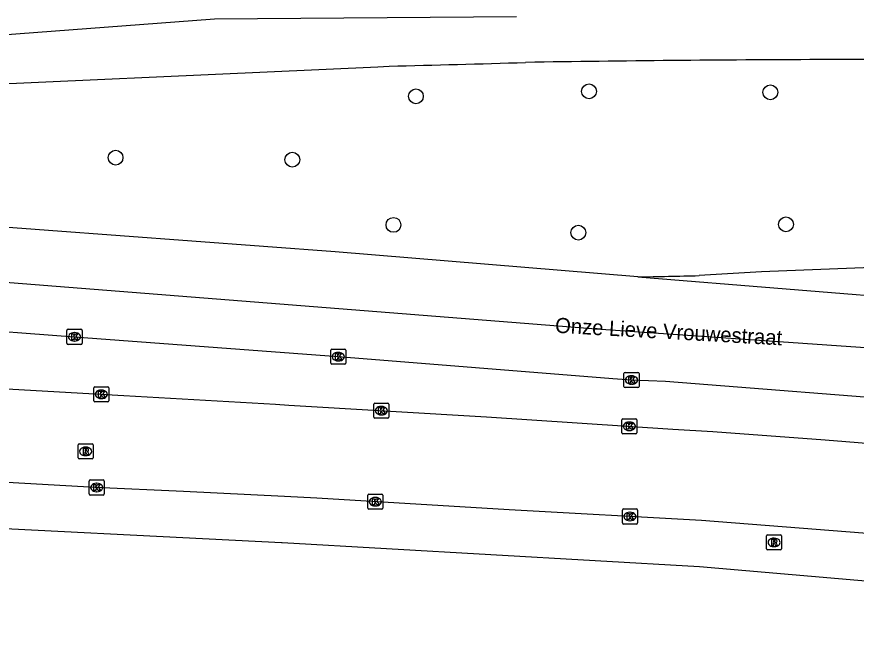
# Model space of a CAD drawing. Extents: x 161243 to 161752, y 384138 to 384885.
# Drawn here: x 161530.1 to 161585.6, y 384837.7 to 384878.9 of the extents above; entities that cross this region are included whole.
import ezdxf

# ---------------------------------------------------------------- set-up
doc = ezdxf.new("R2010")
doc.units = 0
for name, color, linetype in [('IMGEO_Boom', 7, 'Continuous'), ('IMGEO_Kolk', 7, 'Continuous'), ('IMGEO_Openbare_ruimte_label', 7, 'Continuous'), ('IMGEO_Rijbaan_lokaal_open', 7, 'Continuous'), ('IMGEO_Rijbaan_regionaal_gesloten', 7, 'Continuous'), ('IMGEO_Rioolput', 7, 'Continuous'), ('IMGEO_Voetpad_open', 7, 'Continuous')]:
    doc.layers.add(name, color=color, linetype=linetype)

msp = doc.modelspace()

# ---------------------------------------------------------------- linework, layer by layer
at = {"layer": 'IMGEO_Boom'}
for centre in [(161556.501, 384873.684), (161567.935, 384874.007), (161579.91, 384873.948), (161536.666, 384869.629), (161548.337, 384869.493), (161555.019, 384865.185), (161580.94, 384865.219), (161567.233, 384864.672)]:
    msp.add_circle(centre, 0.489, dxfattribs=at)
at = {"layer": 'IMGEO_Kolk'}
for p, q in [((161533.454, 384857.365), (161533.454, 384858.217)), ((161533.529, 384858.291), (161534.381, 384858.291)), ((161533.942, 384858.071), (161533.967, 384858.071)), ((161534.455, 384858.217), (161534.455, 384857.365)), ((161533.965, 384857.511), (161533.94, 384857.511)), ((161534.381, 384857.291), (161533.529, 384857.291)), ((161550.872, 384856.052), (161550.872, 384856.904)), ((161550.947, 384856.978), (161551.799, 384856.978)), ((161551.873, 384856.904), (161551.873, 384856.052)), ((161551.36, 384856.758), (161551.385, 384856.758)), ((161551.799, 384855.978), (161550.947, 384855.978)), ((161551.383, 384856.198), (161551.358, 384856.198)), ((161570.241, 384854.51), (161570.241, 384855.362)), ((161570.316, 384855.436), (161571.168, 384855.436)), ((161570.729, 384855.216), (161570.754, 384855.216)), ((161571.242, 384855.362), (161571.242, 384854.51)), ((161570.752, 384854.656), (161570.727, 384854.656)), ((161535.222, 384853.563), (161535.222, 384854.415)), ((161535.297, 384854.489), (161536.149, 384854.489)), ((161535.71, 384854.269), (161535.735, 384854.269)), ((161536.223, 384854.415), (161536.223, 384853.563)), ((161571.168, 384854.436), (161570.316, 384854.436)), ((161535.733, 384853.709), (161535.708, 384853.709)), ((161536.149, 384853.489), (161535.297, 384853.489)), ((161553.718, 384852.484), (161553.718, 384853.336)), ((161553.793, 384853.41), (161554.645, 384853.41)), ((161554.206, 384853.19), (161554.231, 384853.19)), ((161554.719, 384853.336), (161554.719, 384852.484)), ((161554.229, 384852.63), (161554.204, 384852.63)), ((161554.645, 384852.41), (161553.793, 384852.41)), ((161570.098, 384851.453), (161570.098, 384852.305)), ((161570.173, 384852.379), (161571.025, 384852.379)), ((161570.586, 384852.159), (161570.611, 384852.159)), ((161571.099, 384852.305), (161571.099, 384851.453)), ((161571.025, 384851.379), (161570.173, 384851.379)), ((161570.609, 384851.599), (161570.584, 384851.599)), ((161534.918, 384847.403), (161534.918, 384848.255)), ((161534.993, 384848.329), (161535.845, 384848.329)), ((161535.406, 384848.109), (161535.431, 384848.109)), ((161535.919, 384848.255), (161535.919, 384847.403)), ((161535.429, 384847.549), (161535.404, 384847.549)), ((161535.845, 384847.329), (161534.993, 384847.329)), ((161553.319, 384846.466), (161553.319, 384847.318)), ((161553.394, 384847.392), (161554.246, 384847.392)), ((161553.807, 384847.172), (161553.832, 384847.172)), ((161554.32, 384847.318), (161554.32, 384846.466)), ((161554.246, 384846.392), (161553.394, 384846.392)), ((161553.83, 384846.612), (161553.805, 384846.612)), ((161570.136, 384845.491), (161570.136, 384846.343)), ((161570.211, 384846.417), (161571.063, 384846.417)), ((161571.137, 384846.343), (161571.137, 384845.491)), ((161570.624, 384846.197), (161570.649, 384846.197)), ((161571.063, 384845.417), (161570.211, 384845.417)), ((161570.647, 384845.637), (161570.622, 384845.637))]:
    msp.add_line(p, q, dxfattribs=at)
for points in [[(161533.454, 384857.365), (161533.454, 384858.217)], [(161533.529, 384858.291), (161534.381, 384858.291)], [(161533.775, 384857.991), (161533.898, 384857.991), (161533.898, 384857.84), (161534.028, 384857.991), (161534.192, 384857.991), (161534.046, 384857.84), (161534.199, 384857.591), (161534.047, 384857.591), (161533.962, 384857.755), (161533.898, 384857.688), (161533.898, 384857.591), (161533.775, 384857.591), (161533.775, 384857.991)], [(161534.455, 384858.217), (161534.455, 384857.365)], [(161534.381, 384857.291), (161533.529, 384857.291)], [(161550.872, 384856.052), (161550.872, 384856.904)], [(161550.947, 384856.978), (161551.799, 384856.978)], [(161551.873, 384856.904), (161551.873, 384856.052)], [(161551.193, 384856.678), (161551.316, 384856.678), (161551.316, 384856.527), (161551.446, 384856.678), (161551.61, 384856.678), (161551.464, 384856.527), (161551.617, 384856.278), (161551.465, 384856.278), (161551.38, 384856.442), (161551.316, 384856.375), (161551.316, 384856.278), (161551.193, 384856.278), (161551.193, 384856.678)], [(161551.799, 384855.978), (161550.947, 384855.978)], [(161570.241, 384854.51), (161570.241, 384855.362)], [(161570.316, 384855.436), (161571.168, 384855.436)], [(161571.242, 384855.362), (161571.242, 384854.51)], [(161570.562, 384855.136), (161570.685, 384855.136), (161570.685, 384854.985), (161570.815, 384855.136), (161570.979, 384855.136), (161570.833, 384854.985), (161570.986, 384854.736), (161570.834, 384854.736), (161570.749, 384854.9), (161570.685, 384854.833), (161570.685, 384854.736), (161570.562, 384854.736), (161570.562, 384855.136)], [(161535.222, 384853.563), (161535.222, 384854.415)], [(161535.297, 384854.489), (161536.149, 384854.489)], [(161535.543, 384854.189), (161535.666, 384854.189), (161535.666, 384854.038), (161535.796, 384854.189), (161535.96, 384854.189), (161535.814, 384854.038), (161535.967, 384853.789), (161535.815, 384853.789), (161535.73, 384853.953), (161535.666, 384853.886), (161535.666, 384853.789), (161535.543, 384853.789), (161535.543, 384854.189)], [(161536.223, 384854.415), (161536.223, 384853.563)], [(161571.168, 384854.436), (161570.316, 384854.436)], [(161536.149, 384853.489), (161535.297, 384853.489)], [(161553.718, 384852.484), (161553.718, 384853.336)], [(161553.793, 384853.41), (161554.645, 384853.41)], [(161554.039, 384853.11), (161554.162, 384853.11), (161554.162, 384852.959), (161554.292, 384853.11), (161554.456, 384853.11), (161554.31, 384852.959), (161554.463, 384852.71), (161554.311, 384852.71), (161554.226, 384852.874), (161554.162, 384852.807), (161554.162, 384852.71), (161554.039, 384852.71), (161554.039, 384853.11)], [(161554.719, 384853.336), (161554.719, 384852.484)], [(161554.645, 384852.41), (161553.793, 384852.41)], [(161570.098, 384851.453), (161570.098, 384852.305)], [(161570.173, 384852.379), (161571.025, 384852.379)], [(161570.419, 384852.079), (161570.542, 384852.079), (161570.542, 384851.928), (161570.672, 384852.079), (161570.836, 384852.079), (161570.69, 384851.928), (161570.843, 384851.679), (161570.691, 384851.679), (161570.606, 384851.843), (161570.542, 384851.776), (161570.542, 384851.679), (161570.419, 384851.679), (161570.419, 384852.079)], [(161571.099, 384852.305), (161571.099, 384851.453)], [(161571.025, 384851.379), (161570.173, 384851.379)], [(161534.918, 384847.403), (161534.918, 384848.255)], [(161534.993, 384848.329), (161535.845, 384848.329)], [(161535.239, 384848.029), (161535.362, 384848.029), (161535.362, 384847.878), (161535.492, 384848.029), (161535.656, 384848.029), (161535.51, 384847.878), (161535.663, 384847.629), (161535.511, 384847.629), (161535.426, 384847.793), (161535.362, 384847.726), (161535.362, 384847.629), (161535.239, 384847.629), (161535.239, 384848.029)], [(161535.919, 384848.255), (161535.919, 384847.403)], [(161535.845, 384847.329), (161534.993, 384847.329)], [(161553.319, 384846.466), (161553.319, 384847.318)], [(161553.394, 384847.392), (161554.246, 384847.392)], [(161553.64, 384847.092), (161553.763, 384847.092), (161553.763, 384846.941), (161553.893, 384847.092), (161554.057, 384847.092), (161553.911, 384846.941), (161554.064, 384846.692), (161553.912, 384846.692), (161553.827, 384846.856), (161553.763, 384846.789), (161553.763, 384846.692), (161553.64, 384846.692), (161553.64, 384847.092)], [(161554.32, 384847.318), (161554.32, 384846.466)], [(161554.246, 384846.392), (161553.394, 384846.392)], [(161570.136, 384845.491), (161570.136, 384846.343)], [(161570.211, 384846.417), (161571.063, 384846.417)], [(161571.137, 384846.343), (161571.137, 384845.491)], [(161570.457, 384846.117), (161570.58, 384846.117), (161570.58, 384845.966), (161570.71, 384846.117), (161570.874, 384846.117), (161570.728, 384845.966), (161570.881, 384845.717), (161570.729, 384845.717), (161570.644, 384845.881), (161570.58, 384845.814), (161570.58, 384845.717), (161570.457, 384845.717), (161570.457, 384846.117)], [(161571.063, 384845.417), (161570.211, 384845.417)]]:
    msp.add_lwpolyline(points, dxfattribs=at)
for centre, start, end in [((161533.531, 384858.215), 91.552, 178.448), ((161533.531, 384858.215), 91.552, 178.448), ((161534.379, 384858.215), 1.552, 88.448), ((161534.379, 384858.215), 1.552, 88.448), ((161533.531, 384857.367), 181.552, 268.448), ((161533.531, 384857.367), 181.552, 268.448), ((161534.379, 384857.367), 271.552, 358.448), ((161534.379, 384857.367), 271.552, 358.448), ((161550.949, 384856.902), 91.552, 178.448), ((161550.949, 384856.902), 91.552, 178.448), ((161551.797, 384856.902), 1.552, 88.448), ((161551.797, 384856.902), 1.552, 88.448), ((161550.949, 384856.054), 181.552, 268.448), ((161550.949, 384856.054), 181.552, 268.448), ((161551.797, 384856.054), 271.552, 358.448), ((161551.797, 384856.054), 271.552, 358.448), ((161570.318, 384855.36), 91.552, 178.448), ((161570.318, 384855.36), 91.552, 178.448), ((161571.166, 384855.36), 1.552, 88.448), ((161571.166, 384855.36), 1.552, 88.448), ((161535.299, 384854.413), 91.552, 178.448), ((161535.299, 384854.413), 91.552, 178.448), ((161536.147, 384854.413), 1.552, 88.448), ((161536.147, 384854.413), 1.552, 88.448), ((161570.318, 384854.512), 181.552, 268.448), ((161570.318, 384854.512), 181.552, 268.448), ((161571.166, 384854.512), 271.552, 358.448), ((161571.166, 384854.512), 271.552, 358.448), ((161535.299, 384853.565), 181.552, 268.448), ((161535.299, 384853.565), 181.552, 268.448), ((161536.147, 384853.565), 271.552, 358.448), ((161536.147, 384853.565), 271.552, 358.448), ((161553.795, 384853.334), 91.552, 178.448), ((161553.795, 384853.334), 91.552, 178.448), ((161554.643, 384853.334), 1.552, 88.448), ((161554.643, 384853.334), 1.552, 88.448), ((161553.795, 384852.486), 181.552, 268.448), ((161553.795, 384852.486), 181.552, 268.448), ((161554.643, 384852.486), 271.552, 358.448), ((161554.643, 384852.486), 271.552, 358.448), ((161570.175, 384852.303), 91.552, 178.448), ((161570.175, 384852.303), 91.552, 178.448), ((161571.023, 384852.303), 1.552, 88.448), ((161571.023, 384852.303), 1.552, 88.448), ((161570.175, 384851.455), 181.552, 268.448), ((161570.175, 384851.455), 181.552, 268.448), ((161571.023, 384851.455), 271.552, 358.448), ((161571.023, 384851.455), 271.552, 358.448), ((161534.995, 384848.253), 91.552, 178.448), ((161534.995, 384848.253), 91.552, 178.448), ((161535.843, 384848.253), 1.552, 88.448), ((161535.843, 384848.253), 1.552, 88.448), ((161534.995, 384847.405), 181.552, 268.448), ((161534.995, 384847.405), 181.552, 268.448), ((161535.843, 384847.405), 271.552, 358.448), ((161535.843, 384847.405), 271.552, 358.448), ((161553.396, 384847.316), 91.552, 178.448), ((161553.396, 384847.316), 91.552, 178.448), ((161554.244, 384847.316), 1.552, 88.448), ((161554.244, 384847.316), 1.552, 88.448), ((161553.396, 384846.468), 181.552, 268.448), ((161553.396, 384846.468), 181.552, 268.448), ((161554.244, 384846.468), 271.552, 358.448), ((161554.244, 384846.468), 271.552, 358.448), ((161570.213, 384846.341), 91.552, 178.448), ((161570.213, 384846.341), 91.552, 178.448), ((161571.061, 384846.341), 1.552, 88.448), ((161571.061, 384846.341), 1.552, 88.448), ((161570.213, 384845.493), 181.552, 268.448), ((161570.213, 384845.493), 181.552, 268.448), ((161571.061, 384845.493), 271.552, 358.448), ((161571.061, 384845.493), 271.552, 358.448)]:
    msp.add_arc(centre, 0.0765, start, end, dxfattribs=at)
for centre, major_axis, ratio, start_param, end_param in [((161533.941, 384857.791), (-0.387, 0.002), 0.722429, 4.712389, 7.853982), ((161533.966, 384857.791), (-0.39, 0.002), 0.717154, 1.570796, 4.712389), ((161551.359, 384856.478), (-0.387, 0.002), 0.722429, 4.712389, 7.853982), ((161551.384, 384856.478), (-0.39, 0.002), 0.717154, 1.570796, 4.712389), ((161570.728, 384854.936), (-0.387, 0.002), 0.722429, 4.712389, 7.853982), ((161570.753, 384854.936), (-0.39, 0.002), 0.717154, 1.570796, 4.712389), ((161535.709, 384853.989), (-0.387, 0.002), 0.722429, 4.712389, 7.853982), ((161535.734, 384853.989), (-0.39, 0.002), 0.717154, 1.570796, 4.712389), ((161554.205, 384852.91), (-0.387, 0.002), 0.722429, 4.712389, 7.853982), ((161554.23, 384852.91), (-0.39, 0.002), 0.717154, 1.570796, 4.712389), ((161570.585, 384851.879), (-0.387, 0.002), 0.722429, 4.712389, 7.853982), ((161570.61, 384851.879), (-0.39, 0.002), 0.717154, 1.570796, 4.712389), ((161535.405, 384847.829), (-0.387, 0.002), 0.722429, 4.712389, 7.853982), ((161535.43, 384847.829), (-0.39, 0.002), 0.717154, 1.570796, 4.712389), ((161553.806, 384846.892), (-0.387, 0.002), 0.722429, 4.712389, 7.853982), ((161553.831, 384846.892), (-0.39, 0.002), 0.717154, 1.570796, 4.712389), ((161570.623, 384845.917), (-0.387, 0.002), 0.722429, 4.712389, 7.853982), ((161570.648, 384845.917), (-0.39, 0.002), 0.717154, 1.570796, 4.712389)]:
    msp.add_ellipse(centre, major_axis=major_axis, ratio=ratio, start_param=start_param, end_param=end_param, dxfattribs=at)
at = {"layer": 'IMGEO_Rijbaan_lokaal_open'}
for points in [[(161432.691, 384858.617), (161443.897, 384858.139), (161457.123, 384857.598), (161464.496, 384857.284), (161488.747, 384856.252), (161495.954, 384855.908), (161500.984, 384855.619), (161518.06, 384854.968), (161526.784, 384854.51), (161537.21, 384853.901), (161547.23, 384853.329), (161548.117, 384853.276), (161561.161, 384852.491), (161573.48, 384851.691), (161576.121, 384851.539), (161583.525, 384850.98), (161591.436, 384850.345), (161599.97, 384849.634), (161609.304, 384848.897), (161621.915, 384847.716), (161637.662, 384846.256), (161645.218, 384845.76), (161654.603, 384845.532), (161661.029, 384846.084)], [(161632.436, 384840.682), (161616.429, 384842.146), (161606.018, 384843.165), (161590.517, 384844.456), (161575.357, 384845.656), (161562.667, 384846.361), (161549.947, 384847.125), (161547.823, 384847.234), (161541.147, 384847.577), (161535.307, 384847.835), (161519.427, 384848.731), (161508.267, 384849.216), (161502.488, 384849.552), (161500, 384849.668), (161499.426, 384849.695)]]:
    msp.add_lwpolyline(points, dxfattribs=at)
at = {"layer": 'IMGEO_Rijbaan_regionaal_gesloten'}
for points in [[(161563.138, 384878.938), (161543.2, 384878.777), (161524.222, 384877.345), (161512.226, 384876.808), (161497.186, 384877.166), (161481.609, 384877.166), (161467.536, 384877.915), (161467.518, 384877.993)], [(161494.845, 384873.396), (161507.854, 384873.67), (161520.825, 384874.142), (161553.985, 384875.638), (161554.741, 384875.672)], [(161571.148, 384861.746), (161551.158, 384863.399), (161532.245, 384864.805), (161511.027, 384866.396), (161504.31, 384866.9), (161484.365, 384868.354), (161483.247, 384868.441)], [(161720.414, 384842.06), (161663.633, 384849.838), (161597.297, 384856.281), (161568.402, 384858.295), (161503.74, 384863.414), (161467.959, 384864.205)], [(161654.748, 384858.736), (161646.577, 384859.324), (161637.725, 384859.857), (161625.166, 384860.619), (161617.076, 384861.152), (161611.12, 384861.635), (161603.971, 384862.003), (161595.945, 384862.435), (161592.236, 384862.6), (161579.329, 384862.087), (161575.207, 384861.834)], [(161571.148, 384861.746), (161610.346, 384858.579), (161622.051, 384857.564), (161629.564, 384856.913), (161674.127, 384851.959), (161681.32, 384851.152)], [(161499.371, 384860.47), (161509.567, 384859.646), (161533.955, 384857.791), (161551.373, 384856.478), (161569.508, 384855.04), (161570.742, 384854.936), (161572.993, 384854.851), (161590.878, 384853.444), (161606.841, 384852.059), (161622.232, 384850.751), (161627.655, 384850.205), (161638.043, 384849.1), (161645.472, 384848.465), (161650.082, 384848.059), (161654.755, 384847.767), (161654.704, 384847.64), (161659.708, 384847.081), (161661.029, 384846.96)]]:
    msp.add_lwpolyline(points, dxfattribs=at)
for centre, radius, start, end in [((161496.306, 387152.999), 2278.077, 271.469861, 271.696532), ((161586.952, 383468.163), 1407.949, 90.15553, 90.944232), ((161586.39, 384469.793), 406.327, 87.55773, 90.45974), ((161532.595, 386733.642), 1872.293, 271.179869, 271.304112)]:
    msp.add_arc(centre, radius, start, end, dxfattribs=at)
at = {"layer": 'IMGEO_Rioolput'}
for p, q in [((161534.185, 384849.794), (161534.185, 384850.646)), ((161534.26, 384850.72), (161535.112, 384850.72)), ((161534.673, 384850.5), (161534.698, 384850.5)), ((161535.186, 384850.646), (161535.186, 384849.794)), ((161535.112, 384849.72), (161534.26, 384849.72)), ((161534.696, 384849.94), (161534.671, 384849.94)), ((161579.731, 384844.703), (161580.583, 384844.703)), ((161579.656, 384843.777), (161579.656, 384844.629)), ((161580.144, 384844.483), (161580.169, 384844.483)), ((161580.657, 384844.629), (161580.657, 384843.777)), ((161580.583, 384843.703), (161579.731, 384843.703)), ((161580.167, 384843.923), (161580.142, 384843.923))]:
    msp.add_line(p, q, dxfattribs=at)
for points in [[(161534.185, 384849.794), (161534.185, 384850.646)], [(161534.26, 384850.72), (161535.112, 384850.72)], [(161534.774, 384850.418), (161534.522, 384850.42), (161534.522, 384850.02)], [(161534.7, 384850.339), (161534.646, 384850.339), (161534.646, 384850.258)], [(161534.646, 384850.258), (161534.698, 384850.258)], [(161535.186, 384850.646), (161535.186, 384849.794)], [(161535.112, 384849.72), (161534.26, 384849.72)], [(161534.522, 384850.02), (161534.646, 384850.02), (161534.646, 384850.182), (161534.657, 384850.182)], [(161534.704, 384850.153), (161534.775, 384850.02), (161534.915, 384850.02), (161534.85, 384850.146)], [(161579.731, 384844.703), (161580.583, 384844.703)], [(161579.656, 384843.777), (161579.656, 384844.629)], [(161580.245, 384844.401), (161579.993, 384844.403), (161579.993, 384844.003)], [(161579.993, 384844.003), (161580.117, 384844.003), (161580.117, 384844.165), (161580.128, 384844.165)], [(161580.171, 384844.322), (161580.117, 384844.322), (161580.117, 384844.241)], [(161580.117, 384844.241), (161580.169, 384844.241)], [(161580.175, 384844.136), (161580.246, 384844.003), (161580.386, 384844.003), (161580.321, 384844.129)], [(161580.657, 384844.629), (161580.657, 384843.777)], [(161580.583, 384843.703), (161579.731, 384843.703)]]:
    msp.add_lwpolyline(points, dxfattribs=at)
for centre, radius, start, end in [((161534.262, 384850.644), 0.0765, 91.552, 178.448), ((161534.262, 384850.644), 0.0765, 91.552, 178.448), ((161534.682, 384850.447), 0.19, 274.7715, 282.9687), ((161534.706, 384850.243), 0.0964, 77.0061, 93.1865), ((161534.72, 384850.3), 0.0378, 276.6634, 79.6772), ((161534.773, 384850.308), 0.109, 350.3612, 89.416), ((161534.771, 384850.308), 0.112, 277.5842, 350.9817), ((161535.11, 384850.644), 0.0765, 1.552, 88.448), ((161535.11, 384850.644), 0.0765, 1.552, 88.448), ((161534.262, 384849.796), 0.0765, 181.552, 268.448), ((161534.262, 384849.796), 0.0765, 181.552, 268.448), ((161534.656, 384850.129), 0.0533, 26.0293, 88.6989), ((161534.755, 384850.093), 0.108, 29.5134, 73.7905), ((161535.11, 384849.796), 0.0765, 271.552, 358.448), ((161535.11, 384849.796), 0.0765, 271.552, 358.448), ((161579.733, 384844.627), 0.0765, 91.552, 178.448), ((161579.733, 384844.627), 0.0765, 91.552, 178.448), ((161580.581, 384844.627), 0.0765, 1.552, 88.448), ((161580.581, 384844.627), 0.0765, 1.552, 88.448), ((161580.127, 384844.112), 0.0533, 26.0293, 88.6989), ((161580.153, 384844.43), 0.19, 274.7715, 282.9687), ((161580.177, 384844.226), 0.0964, 77.0061, 93.1865), ((161580.191, 384844.283), 0.0378, 276.6634, 79.6772), ((161580.244, 384844.291), 0.109, 350.3612, 89.416), ((161580.242, 384844.291), 0.112, 277.5842, 350.9817), ((161580.226, 384844.076), 0.108, 29.5134, 73.7905), ((161579.733, 384843.779), 0.0765, 181.552, 268.448), ((161579.733, 384843.779), 0.0765, 181.552, 268.448), ((161580.581, 384843.779), 0.0765, 271.552, 358.448), ((161580.581, 384843.779), 0.0765, 271.552, 358.448)]:
    msp.add_arc(centre, radius, start, end, dxfattribs=at)
for centre, major_axis, ratio, start_param, end_param in [((161534.672, 384850.22), (-0.387, 0.002), 0.722429, 4.712389, 7.853982), ((161534.697, 384850.22), (-0.39, 0.002), 0.717154, 1.570796, 4.712389), ((161580.143, 384844.203), (-0.387, 0.002), 0.722429, 4.712389, 7.853982), ((161580.168, 384844.203), (-0.39, 0.002), 0.717154, 1.570796, 4.712389)]:
    msp.add_ellipse(centre, major_axis=major_axis, ratio=ratio, start_param=start_param, end_param=end_param, dxfattribs=at)
at = {"layer": 'IMGEO_Voetpad_open'}
msp.add_lwpolyline([(161498.947, 384846.657), (161547.634, 384844.19), (161547.675, 384844.188), (161575.224, 384842.605), (161630.585, 384837.825), (161632.138, 384837.674)], dxfattribs=at)

# ---------------------------------------------------------------- texts
at = {"layer": 'IMGEO_Openbare_ruimte_label'}
msp.add_text('Onze Lieve Vrouwestraat', height=1, rotation=356.7884, dxfattribs=at).set_placement((161565.673, 384858.063))

doc.saveas('drawing.dxf')
